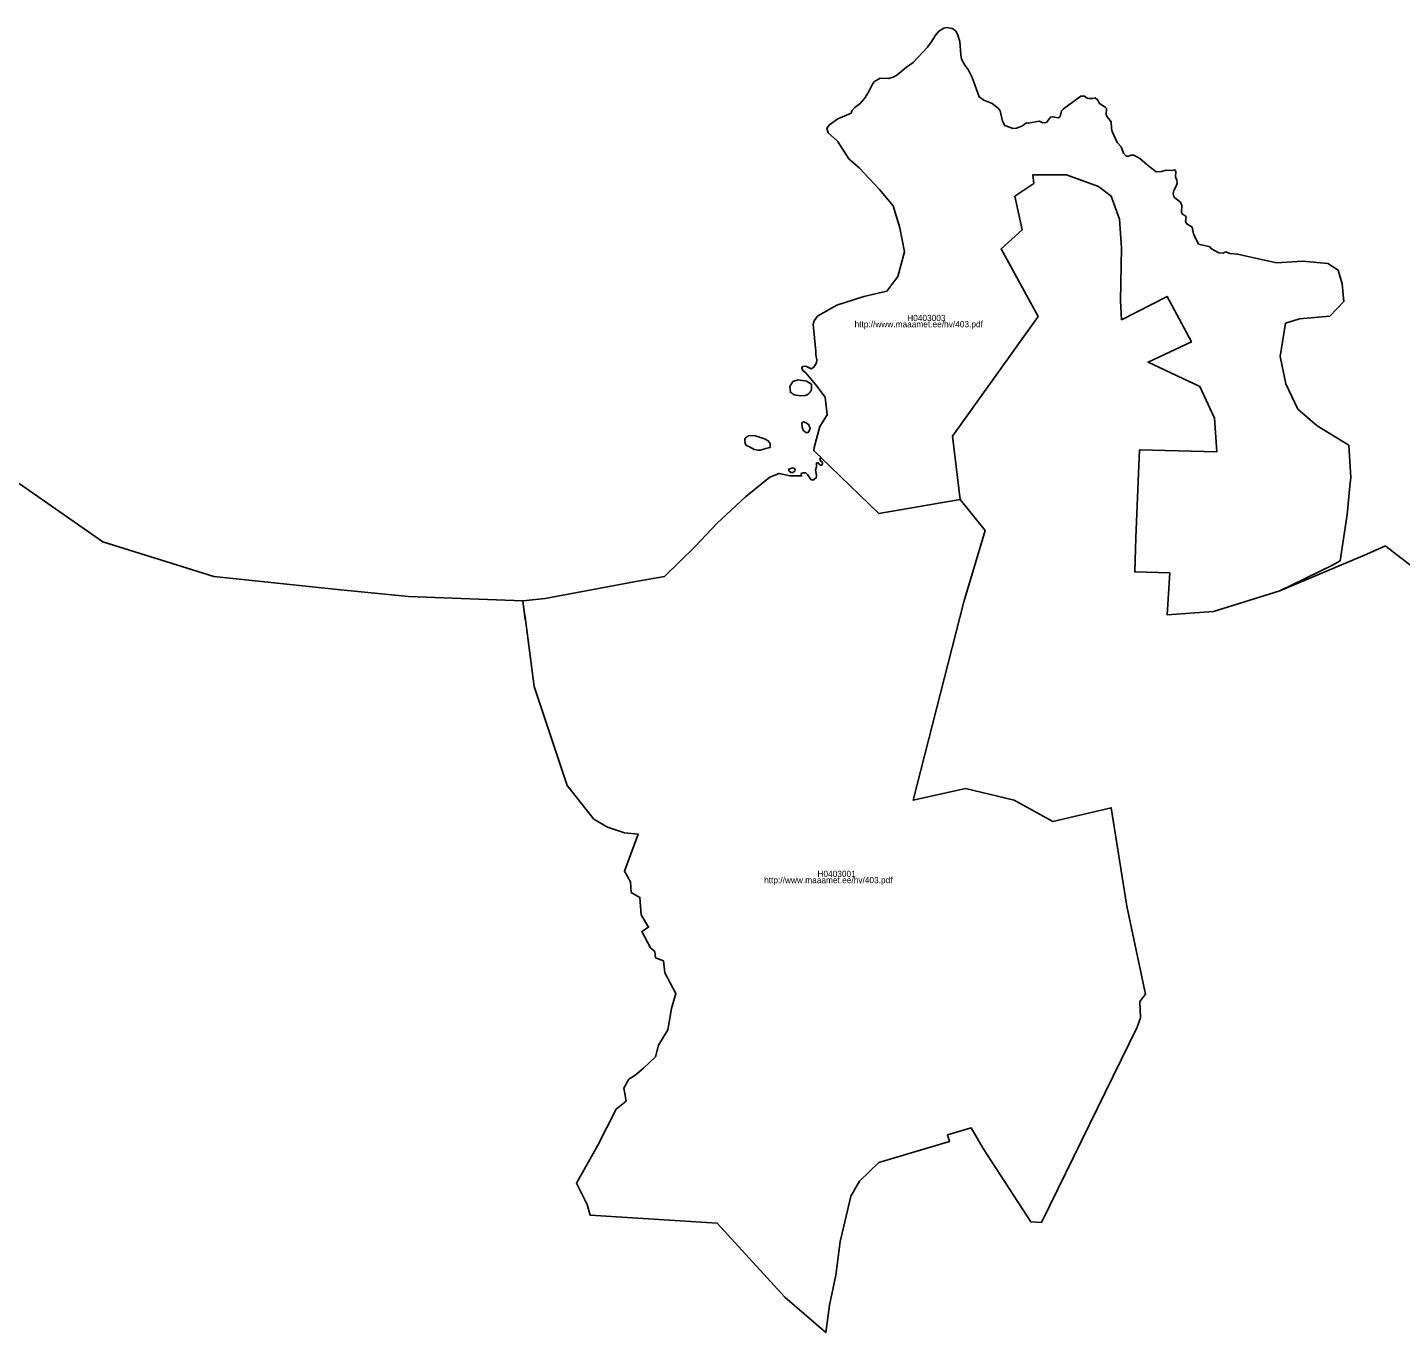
# Model space of a CAD drawing. Extents: x 369010 to 739155, y 6377141 to 6634081.
# Drawn here: x 420281 to 425807, y 6491116 to 6496369 of the extents above; entities that cross this region are included whole.
import ezdxf

# ---------------------------------------------------------------- set-up
doc = ezdxf.new("R2010")
doc.units = 0
for name, color, linetype in [('H_LINK', 7, 'Continuous'), ('H_PIIR', 7, 'Continuous'), ('H_TUNNUS', 7, 'Continuous')]:
    doc.layers.add(name, color=color, linetype=linetype)

msp = doc.modelspace()

# ---------------------------------------------------------------- linework, layer by layer
at = {"layer": 'H_PIIR'}
for points in [[(423474.0114, 6494638.1015), (423474.34, 6494638.5947), (423445.83, 6494664.96), (423447.2909, 6494677.9142), (423469.516, 6494762.581), (423500.2077, 6494809.1478), (423491.741, 6494880.0563), (423453.641, 6494929.798), (423414.26, 6494978.1947), (423401.3001, 6494987.9146), (423397.7599, 6494997.3447), (423400.41, 6495004.1146), (423413.9601, 6495004.9946), (423435.1699, 6494994.3947), (423446.3601, 6495000.8747), (423456.6701, 6495018.5446), (423457.8501, 6495031.5047), (423453.7199, 6495050.9447), (423453.7199, 6495063.9046), (423443.4201, 6495174.6546), (423446.66, 6495187.6146), (423460.2001, 6495206.4646), (423464.6199, 6495209.4046), (423539.0574, 6495250.9036), (423647.5368, 6495285.2995), (423740.1412, 6495307.7892), (423783.7975, 6495365.9976), (423810.2559, 6495465.2166), (423791.735, 6495561.7897), (423765.2766, 6495650.4253), (423709.714, 6495716.5712), (423628.97, 6495803.7746), (423587.44, 6495839.4146), (423541.5001, 6495911.5746), (423503.5, 6495945.1546), (423498.2001, 6495963.1247), (423508.8, 6495976.9647), (423542.38, 6496001.1146), (423596.58, 6496024.0946), (423599.52, 6496032.9247), (423610.7101, 6496047.0646), (423632.21, 6496063.2646), (423649.8799, 6496082.9946), (423665.79, 6496108.9146), (423682.8701, 6496142.4946), (423690.2399, 6496151.0346), (423712.9201, 6496165.1747), (423746.49, 6496162.8147), (423765.64, 6496168.4146), (423780.66, 6496176.6647), (423818.9499, 6496209.0547), (423846.0499, 6496227.3246), (423903.48, 6496290.0546), (423918.5, 6496309.2046), (423936.47, 6496338.6546), (423949.72, 6496353.9647), (423969.4599, 6496366.3446), (423980.0601, 6496368.6946), (424002.4399, 6496365.1646), (424008.3401, 6496362.2146), (424017.17, 6496353.3847), (424024.53, 6496341.6047), (424033.96, 6496312.1446), (424037.2001, 6496259.1247), (424040.4399, 6496241.4547), (424053.99, 6496217.0147), (424066.65, 6496199.3347), (424083.44, 6496167.8246), (424111.4199, 6496088.8847), (424130.27, 6496076.5146), (424163.56, 6496062.0846), (424187.7101, 6496044.1147), (424196.2499, 6496032.9247), (424205.0801, 6495991.1046), (424214.8001, 6495974.6046), (424248.68, 6495962.5347), (424262.2201, 6495964.0046), (424283.4299, 6495971.0746), (424302.28, 6495984.6247), (424309.06, 6495983.1446), (424352.94, 6495991.6946), (424367.6699, 6495985.2147), (424382.0999, 6495986.3847), (424398.3001, 6496007.8946), (424408.31, 6496009.6546), (424430.7001, 6496005.2447), (424436.8799, 6496010.8346), (424443.07, 6496032.6346), (424450.7299, 6496040.8746), (424520.24, 6496092.1246), (424535.26, 6496092.7146), (424546.16, 6496084.7646), (424553.81, 6496082.7047), (424567.9501, 6496082.7047), (424578.2599, 6496085.3546), (424588.5699, 6496076.5146), (424595.34, 6496062.0846), (424618.91, 6496048.2446), (424623.62, 6496042.3547), (424622.44, 6496018.4947), (424626.56, 6496008.7747), (424642.47, 6495988.7446), (424643.65, 6495964.0046), (424646.59, 6495950.4547), (424666.92, 6495905.0946), (424682.8201, 6495888.0146), (424692.24, 6495862.0946), (424703.73, 6495850.6047), (424712.27, 6495850.3146), (424723.47, 6495854.1447), (424733.4799, 6495855.0246), (424757.6299, 6495841.4747), (424787.38, 6495815.5647), (424824.2001, 6495787.5746), (424844.8199, 6495789.0547), (424864.25, 6495794.3546), (424886.9299, 6495792.8847), (424899.0099, 6495795.2347), (424903.1301, 6495789.3446), (424901.07, 6495767.8446), (424906.6701, 6495753.7047), (424907.8401, 6495740.7446), (424903.43, 6495727.2047), (424895.18, 6495713.0646), (424892.2401, 6495698.9247), (424895.18, 6495688.6147), (424899.5999, 6495682.7247), (424921.98, 6495665.3446), (424926.6999, 6495652.3846), (424926.1099, 6495625.2946), (424927.8699, 6495619.1046), (424944.0699, 6495607.6146), (424942.01, 6495587.5847), (424947.6101, 6495578.1646), (424969.11, 6495564.6147), (424974.7001, 6495538.6946), (424994.58, 6495496.6546), (425036.26, 6495486.5647), (425039.5, 6495486.2646), (425045.98, 6495477.4347), (425076.3201, 6495462.1146), (425095.46, 6495459.7646), (425098.1199, 6495463.2946), (425104.0001, 6495465.0646), (425120.5, 6495458.8747), (425151.43, 6495456.8146), (425308.41, 6495421.7646), (425413.1049, 6495427.5134), (425514.7051, 6495418.7821), (425556.774, 6495391.7945), (425571.8553, 6495336.2319), (425578.999, 6495265.588), (425522.6427, 6495206.8504), (425400.4049, 6495195.4733), (425344.8423, 6495178.2754), (425322.3527, 6495044.6605), (425346.1652, 6494934.8582), (425393.7903, 6494832.9934), (425471.8426, 6494765.5245), (425598.8428, 6494687.4723), (425606.9457, 6494556.834), (425603.6384, 6494522.4381), (425593.055, 6494408.0056), (425563.9508, 6494222.1354), (425533.95, 6494204.97), (425321.522, 6494101.4333), (425321.3199, 6494101.37), (425054.9301, 6494017.9), (424867.71, 6494005.14), (424878.3501, 6494173.2099), (424737.93, 6494177.47), (424742.1901, 6494315.7599), (424757.0799, 6494668.9101), (425067.69, 6494660.4), (425059.18, 6494796.56), (424999.61, 6494924.22), (424791.1199, 6495022.0801), (424965.57, 6495102.93), (424867.71, 6495285.89), (424684.74, 6495192.2801), (424680.4901, 6495268.8699), (424684.74, 6495481.62), (424676.23, 6495596.51), (424642.19, 6495690.1199), (424591.13, 6495728.41), (424463.4801, 6495775.22), (424327.3201, 6495775.22), (424331.57, 6495741.18), (424254.98, 6495690.1199), (424284.77, 6495553.9599), (424199.6699, 6495477.37), (424348.5899, 6495205.05), (424003.94, 6494724.2299), (424035.2, 6494469.47), (423707.1101, 6494411.84), (423474.5901, 6494637.54)], [(423349.2626, 6494923.448), (423361.9626, 6494943.5564), (423383.1294, 6494949.9064), (423416.9961, 6494945.6731), (423436.0461, 6494932.9731), (423437.1045, 6494919.2147), (423437.1045, 6494911.8063), (423431.8128, 6494901.223), (423425.4628, 6494895.9313), (423419.1128, 6494889.5813), (423411.7044, 6494887.4646), (423393.7127, 6494886.4063), (423374.6627, 6494888.523), (423367.2543, 6494890.6396), (423351.3793, 6494900.1647)], [(423416.3356, 6494737.0394), (423404.0884, 6494745.6456), (423398.9577, 6494759.8789), (423397.9647, 6494776.9259), (423404.7502, 6494780.898), (423415.6735, 6494777.5879), (423426.4314, 6494769.8092), (423431.0655, 6494755.0793), (423424.9418, 6494739.3564)], [(423182.7071, 6494724.7456), (423204.5352, 6494726.0685), (423219.0874, 6494722.7612), (423247.5301, 6494712.8393), (423262.0822, 6494705.5632), (423270.0198, 6494693.6569), (423270.0198, 6494678.4434), (423250.8374, 6494673.8132), (423244.2228, 6494671.1673), (423230.3322, 6494667.86), (423221.0717, 6494667.86), (423205.8582, 6494670.5059), (423189.9831, 6494679.1048), (423174.7696, 6494686.3809), (423170.1393, 6494692.9955), (423168.8164, 6494710.1934), (423171.4623, 6494717.4695)], [(423474.0114, 6494638.1015), (423474.5901, 6494637.54), (423707.1101, 6494411.84), (424035.2, 6494469.47), (424135.38, 6494344.18), (424050.2299, 6494056.7801), (423846.34, 6493258.45), (424056.7301, 6493306.0601), (424252.08, 6493258.45), (424407.36, 6493173.2499), (424642.7899, 6493228.38), (424705.4, 6492832.4601), (424780.54, 6492478.1601), (424758, 6492448.0901), (424760.4999, 6492382.9401), (424747.9801, 6492345.3599), (424362.28, 6491558.54), (424319.6999, 6491561.05), (424126.85, 6491856.7301), (424079.2701, 6491939.42), (423984.0901, 6491911.86), (423991.6101, 6491884.2899), (423707.1101, 6491800.1099), (423629.46, 6491724.93), (423594.4, 6491664.8), (423571.86, 6491567.0701), (423551.8199, 6491481.87), (423534.29, 6491346.5599), (423509.2501, 6491226.28), (423494.2201, 6491116.03), (423328.92, 6491258.8599), (423056.43, 6491556.3), (422545.4999, 6491588.8799), (422532.9801, 6491631.48), (422512.94, 6491671.5701), (422490.4, 6491716.67), (422575.5599, 6491867.0199), (422650.6901, 6492014.8601), (422690.77, 6492047.44), (422680.75, 6492100.0599), (422700.7799, 6492135.14), (422725.83, 6492150.18), (422760.8901, 6492180.2399), (422808.48, 6492225.3499), (422821, 6492272.96), (422858.57, 6492334.86), (422873.6, 6492420.06), (422891.1299, 6492480.2), (422846.05, 6492564.4), (422841.0401, 6492612.0101), (422808.48, 6492624.5399), (422805.98, 6492649.6), (422788.4399, 6492664.63), (422753.3801, 6492729.78), (422780.9299, 6492747.33), (422750.8799, 6492797.44), (422745.8701, 6492867.6001), (422710.8, 6492887.6499), (422708.3001, 6492930.25), (422683.25, 6492972.85), (422738.3501, 6493121.9599), (422683.25, 6493126.97), (422615.63, 6493149.51), (422560.5299, 6493182.0701), (422452.83, 6493317.31), (422320.0901, 6493715.54), (422285.21, 6493984.84), (422285.1398, 6493985.3814), (422279.2855, 6494028.0962), (422273.9938, 6494060.9046), (422365.0107, 6494070.4297), (422729.078, 6494138.1631), (422844.4366, 6494158.2715), (422968.2619, 6494279.9801), (423057.162, 6494373.1136), (423171.4623, 6494478.9471), (423268.8291, 6494559.3806), (423306.9292, 6494573.139), (423350.321, 6494563.614), (423396.29, 6494563.7846), (423394.8199, 6494572.9146), (423403.36, 6494576.4546), (423413.9601, 6494575.5647), (423420.74, 6494569.0846), (423433.4, 6494549.3546), (423442.2401, 6494547.2947), (423455.2, 6494555.8346), (423457.2601, 6494567.3246), (423453.1399, 6494586.7646), (423456.0801, 6494599.7147), (423456.0801, 6494615.3247), (423461.97, 6494617.0947), (423471.99, 6494607.3747), (423478.17, 6494607.6746), (423481.12, 6494613.2646), (423480.53, 6494617.0947), (423472.8701, 6494624.4646), (423469.63, 6494631.5247)], [(423359.4022, 6494595.699), (423366.3534, 6494594.5404), (423371.153, 6494588.7478), (423369.829, 6494582.9552), (423361.0573, 6494577.1625), (423353.444, 6494577.4936), (423345.4998, 6494583.7828), (423345.1689, 6494590.4028)]]:
    msp.add_lwpolyline(points, close=True, dxfattribs=at)
msp.add_lwpolyline([(420247.4754, 6494533.0898), (420584.0261, 6494298.1393), (421030.6437, 6494158.4391), (421529.1197, 6494106.5806), (421813.8119, 6494079.0639), (422273.9938, 6494060.9046), (422284.38, 6493984.9146), (422285.1398, 6493985.3814), (422285.21, 6493984.84), (422320.0901, 6493715.54), (422452.83, 6493317.31), (422560.5299, 6493182.0701), (422615.63, 6493149.51), (422683.25, 6493126.97), (422738.3501, 6493121.9599), (422683.25, 6492972.85), (422708.3001, 6492930.25), (422710.8, 6492887.6499), (422745.8701, 6492867.6001), (422750.8799, 6492797.44), (422780.9299, 6492747.33), (422753.3801, 6492729.78), (422788.4399, 6492664.63), (422805.98, 6492649.6), (422808.48, 6492624.5399), (422841.0401, 6492612.0101), (422846.05, 6492564.4), (422891.1299, 6492480.2), (422873.6, 6492420.06), (422858.57, 6492334.86), (422821, 6492272.96), (422808.48, 6492225.3499), (422760.8901, 6492180.2399), (422725.83, 6492150.18), (422700.7799, 6492135.14), (422680.75, 6492100.0599), (422690.77, 6492047.44), (422650.6901, 6492014.8601), (422575.5599, 6491867.0199), (422490.4, 6491716.67), (422512.94, 6491671.5701), (422532.9801, 6491631.48), (422545.4999, 6491588.8799), (423056.43, 6491556.3), (423328.92, 6491258.8599), (423494.2201, 6491116.03), (423509.2501, 6491226.28), (423534.29, 6491346.5599), (423551.8199, 6491481.87), (423571.86, 6491567.0701), (423594.4, 6491664.8), (423629.46, 6491724.93), (423707.1101, 6491800.1099), (423991.6101, 6491884.2899), (423984.0901, 6491911.86), (424079.2701, 6491939.42), (424126.85, 6491856.7301), (424319.6999, 6491561.05), (424362.28, 6491558.54), (424747.9801, 6492345.3599), (424760.4999, 6492382.9401), (424758, 6492448.0901), (424780.54, 6492478.1601), (424705.4, 6492832.4601), (424642.7899, 6493228.38), (424407.36, 6493173.2499), (424252.08, 6493258.45), (424056.7301, 6493306.0601), (423846.34, 6493258.45), (424050.2299, 6494056.7801), (424135.38, 6494344.18), (424035.2, 6494469.47), (424003.94, 6494724.2299), (424348.5899, 6495205.05), (424199.6699, 6495477.37), (424284.77, 6495553.9599), (424254.98, 6495690.1199), (424331.57, 6495741.18), (424327.3201, 6495775.22), (424463.4801, 6495775.22), (424591.13, 6495728.41), (424642.19, 6495690.1199), (424676.23, 6495596.51), (424684.74, 6495481.62), (424680.4901, 6495268.8699), (424684.74, 6495192.2801), (424867.71, 6495285.89), (424965.57, 6495102.93), (424791.1199, 6495022.0801), (424999.61, 6494924.22), (425059.18, 6494796.56), (425067.69, 6494660.4), (424757.0799, 6494668.9101), (424742.1901, 6494315.7599), (424737.93, 6494177.47), (424878.3501, 6494173.2099), (424867.71, 6494005.14), (425054.9301, 6494017.9), (425321.3199, 6494101.37), (425321.522, 6494101.4333), (425321.62, 6494100.8247), (425671.6254, 6494249.1064), (425746.7672, 6494281.9148), (425749.3072, 6494279.904), (425885.3034, 6494175.658)], dxfattribs=at)

# ---------------------------------------------------------------- texts
at = {"layer": 'H_LINK'}
msp.add_text('http://www.maaamet.ee/hv/403.pdf', height=25, rotation=0, dxfattribs=at).set_placement((423609.815, 6495161.9173))
msp.add_text('http://www.maaamet.ee/hv/403.pdf', height=25, dxfattribs=at).set_placement((423246.0428, 6492924.6162))
at = {"layer": 'H_TUNNUS'}
msp.add_text('H0403003', height=25, rotation=0, dxfattribs=at).set_placement((423821.6696, 6495186.9173))
msp.add_text('H0403001', height=25, dxfattribs=at).set_placement((423460.3968, 6492949.6162))

doc.saveas('drawing.dxf')
